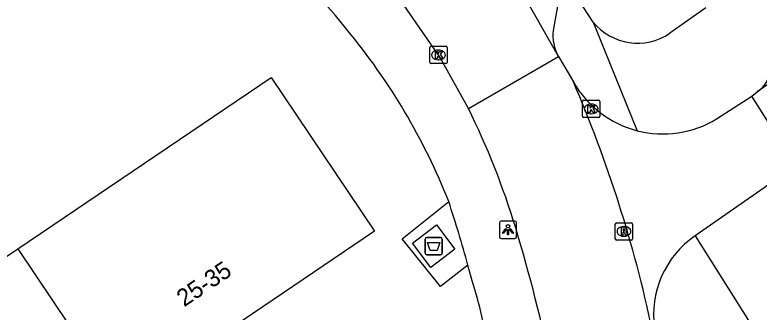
# Model space of a CAD drawing. Extents: x 157466 to 158888, y 383063 to 384677.
# Drawn here: x 157968.71 to 158011.77, y 383458.96 to 383476.12 of the extents above; entities that cross this region are included whole.
import ezdxf

# ---------------------------------------------------------------- set-up
doc = ezdxf.new("R2010")
doc.units = 0
for name, color, linetype in [('IMGEO_Afval_apart_plaats', 7, 'Continuous'), ('IMGEO_Kolk', 7, 'Continuous'), ('IMGEO_Lichtpunt', 7, 'Continuous'), ('IMGEO_Pand', 7, 'Continuous'), ('IMGEO_Pand_nummerreeks', 7, 'Continuous'), ('IMGEO_Rijbaan_lokaal_gesloten', 7, 'Continuous'), ('IMGEO_Rijbaan_lokaal_open', 7, 'Continuous'), ('IMGEO_Rioolput', 7, 'Continuous'), ('IMGEO_Voetpad_gesloten', 7, 'Continuous'), ('IMGEO_Voetpad_open', 7, 'Continuous')]:
    doc.layers.add(name, color=color, linetype=linetype)

msp = doc.modelspace()

# ---------------------------------------------------------------- linework, layer by layer
at = {"layer": 'IMGEO_Afval_apart_plaats'}
for p, q in [((157992.447, 383462.369), (157992.447, 383463.169)), ((157992.447, 383463.169), (157992.447, 383462.369)), ((157992.547, 383463.269), (157993.337, 383463.269)), ((157993.337, 383463.269), (157992.547, 383463.269)), ((157993.437, 383463.169), (157993.437, 383462.369)), ((157993.437, 383462.369), (157993.437, 383463.169)), ((157993.337, 383462.269), (157992.547, 383462.269)), ((157992.547, 383462.269), (157993.337, 383462.269))]:
    msp.add_line(p, q, dxfattribs=at)
msp.add_lwpolyline([(157992.59, 383462.983), (157993.294, 383462.983), (157993.145, 383462.513), (157992.739, 383462.513), (157992.59, 383462.983)], dxfattribs=at)
for centre, start, end in [((157992.547, 383463.169), 90, 180), ((157992.547, 383463.169), 90, 180), ((157993.337, 383463.169), 0, 90), ((157993.337, 383463.169), 360, 90), ((157992.547, 383462.369), 180, 270), ((157992.547, 383462.369), 180, 270), ((157993.337, 383462.369), 270, 0), ((157993.337, 383462.369), 270, 0)]:
    msp.add_arc(centre, 0.1, start, end, dxfattribs=at)
at = {"layer": 'IMGEO_Kolk'}
for p, q in [((157992.721, 383473.382), (157992.721, 383474.234)), ((157992.796, 383474.308), (157993.648, 383474.308)), ((157993.722, 383474.234), (157993.722, 383473.382)), ((157993.209, 383474.088), (157993.234, 383474.088)), ((157993.232, 383473.528), (157993.207, 383473.528)), ((157993.648, 383473.308), (157992.796, 383473.308)), ((158001.55, 383470.266), (158001.55, 383471.118)), ((158001.625, 383471.192), (158002.477, 383471.192)), ((158002.038, 383470.972), (158002.063, 383470.972)), ((158002.551, 383471.118), (158002.551, 383470.266)), ((158002.061, 383470.412), (158002.036, 383470.412)), ((158002.477, 383470.192), (158001.625, 383470.192))]:
    msp.add_line(p, q, dxfattribs=at)
for points in [[(157992.721, 383473.382), (157992.721, 383474.234)], [(157992.796, 383474.308), (157993.648, 383474.308)], [(157993.722, 383474.234), (157993.722, 383473.382)], [(157993.042, 383474.008), (157993.165, 383474.008), (157993.165, 383473.857), (157993.295, 383474.008), (157993.459, 383474.008), (157993.313, 383473.857), (157993.466, 383473.608), (157993.314, 383473.608), (157993.229, 383473.772), (157993.165, 383473.705), (157993.165, 383473.608), (157993.042, 383473.608), (157993.042, 383474.008)], [(157993.648, 383473.308), (157992.796, 383473.308)], [(158001.55, 383470.266), (158001.55, 383471.118)], [(158001.625, 383471.192), (158002.477, 383471.192)], [(158001.871, 383470.892), (158001.994, 383470.892), (158001.994, 383470.741), (158002.124, 383470.892), (158002.288, 383470.892), (158002.142, 383470.741), (158002.295, 383470.492), (158002.143, 383470.492), (158002.058, 383470.656), (158001.994, 383470.589), (158001.994, 383470.492), (158001.871, 383470.492), (158001.871, 383470.892)], [(158002.551, 383471.118), (158002.551, 383470.266)], [(158002.477, 383470.192), (158001.625, 383470.192)]]:
    msp.add_lwpolyline(points, dxfattribs=at)
for centre, start, end in [((157992.798, 383474.232), 91.552, 178.448), ((157992.798, 383474.232), 91.552, 178.448), ((157993.646, 383474.232), 1.552, 88.448), ((157993.646, 383474.232), 1.552, 88.448), ((157992.798, 383473.384), 181.552, 268.448), ((157992.798, 383473.384), 181.552, 268.448), ((157993.646, 383473.384), 271.552, 358.448), ((157993.646, 383473.384), 271.552, 358.448), ((158001.627, 383471.116), 91.552, 178.448), ((158001.627, 383471.116), 91.552, 178.448), ((158002.475, 383471.116), 1.552, 88.448), ((158002.475, 383471.116), 1.552, 88.448), ((158001.627, 383470.268), 181.552, 268.448), ((158001.627, 383470.268), 181.552, 268.448), ((158002.475, 383470.268), 271.552, 358.448), ((158002.475, 383470.268), 271.552, 358.448)]:
    msp.add_arc(centre, 0.0765, start, end, dxfattribs=at)
for centre, major_axis, ratio, start_param, end_param in [((157993.208, 383473.808), (-0.387, 0.002), 0.722429, 4.712389, 7.853982), ((157993.233, 383473.808), (-0.39, 0.002), 0.717154, 1.570796, 4.712389), ((158002.037, 383470.692), (-0.387, 0.002), 0.722429, 4.712389, 7.853982), ((158002.062, 383470.692), (-0.39, 0.002), 0.717154, 1.570796, 4.712389)]:
    msp.add_ellipse(centre, major_axis=major_axis, ratio=ratio, start_param=start_param, end_param=end_param, dxfattribs=at)
at = {"layer": 'IMGEO_Lichtpunt'}
for p, q in [((157996.743, 383464.118), (157996.743, 383463.311)), ((157996.743, 383464.118), (157996.743, 383463.311)), ((157997.645, 383464.213), (157996.837, 383464.213)), ((157997.645, 383464.213), (157996.837, 383464.213)), ((157997.739, 383463.311), (157997.739, 383464.118)), ((157997.739, 383463.311), (157997.739, 383464.118)), ((157996.837, 383463.217), (157997.645, 383463.217)), ((157996.837, 383463.217), (157997.645, 383463.217))]:
    msp.add_line(p, q, dxfattribs=at)
for points in [[(157997.117, 383463.782), (157997.156, 383463.754), (157996.968, 383463.492), (157996.93, 383463.519), (157997.117, 383463.782)], [(157997.219, 383463.734), (157997.266, 383463.734), (157997.266, 383463.412), (157997.219, 383463.412), (157997.219, 383463.734)], [(157997.329, 383463.754), (157997.367, 383463.781), (157997.554, 383463.519), (157997.515, 383463.491), (157997.329, 383463.754)]]:
    msp.add_lwpolyline(points, dxfattribs=at)
msp.add_circle((157997.242, 383463.916), 0.0994, dxfattribs=at)
for centre, start, end in [((157996.837, 383464.118), 90, 180), ((157996.837, 383464.118), 90, 180), ((157997.645, 383464.118), 0, 90), ((157997.645, 383464.118), 0, 90), ((157996.837, 383463.311), 180, 270), ((157996.837, 383463.311), 180, 270), ((157997.645, 383463.311), 270, 0), ((157997.645, 383463.311), 270, 360)]:
    msp.add_arc(centre, 0.0946, start, end, dxfattribs=at)
at = {"layer": 'IMGEO_Pand'}
for points in [[(157968.869, 383462.612), (157983.54, 383472.513), (157989.524, 383463.625), (157974.853, 383453.724)], [(157954.187, 383452.703), (157968.869, 383462.612)], [(157968.869, 383462.612), (157974.853, 383453.724)]]:
    msp.add_lwpolyline(points, dxfattribs=at)
at = {"layer": 'IMGEO_Rijbaan_lokaal_gesloten'}
for points in [[(157994.947, 383470.721), (157993.279, 383473.713), (157989.701, 383478.888), (157989.562, 383479.045)], [(158000.16, 383473.727), (157998.304, 383476.981)], [(157994.947, 383470.721), (158000.16, 383473.727)], [(158000.16, 383473.727), (158001.025, 383472.251)]]:
    msp.add_lwpolyline(points, dxfattribs=at)
for centre, radius, start, end in [((157953.862, 383450.404), 45.834, 17.0264, 26.3126), ((157897.758, 383433.829), 104.334, 12.05271, 16.7084)]:
    msp.add_arc(centre, radius, start, end, dxfattribs=at)
at = {"layer": 'IMGEO_Rijbaan_lokaal_open'}
for points in [[(158054.318, 383500.98), (158011.667, 383471.672)], [(158011.346, 383471.434), (158011.667, 383471.672)], [(158009.313, 383470.112), (158011.346, 383471.434)], [(158013.925, 383467.527), (158012.545, 383469.533), (158011.346, 383471.434)], [(158013.925, 383467.527), (158012.114, 383466.171), (158010.93, 383465.347), (158008.072, 383463.356)]]:
    msp.add_lwpolyline(points, dxfattribs=at)
for centre, radius, start, end in [((158006.213, 383475.223), 5.978, 209.805, 255.5226), ((157931.831, 383442.331), 75.386, 11.97242, 23.38412), ((158006.212, 383475.217), 5.972, 255.5108, 301.2763), ((158011.159, 383458.806), 5.498, 124.1575, 188.2644)]:
    msp.add_arc(centre, radius, start, end, dxfattribs=at)
at = {"layer": 'IMGEO_Rioolput'}
for p, q in [((158003.452, 383463.189), (158003.452, 383464.041)), ((158003.527, 383464.115), (158004.379, 383464.115)), ((158003.94, 383463.895), (158003.965, 383463.895)), ((158004.453, 383464.041), (158004.453, 383463.189)), ((158004.379, 383463.115), (158003.527, 383463.115)), ((158003.963, 383463.335), (158003.938, 383463.335))]:
    msp.add_line(p, q, dxfattribs=at)
for points in [[(158003.452, 383463.189), (158003.452, 383464.041)], [(158003.527, 383464.115), (158004.379, 383464.115)], [(158004.453, 383464.041), (158004.453, 383463.189)], [(158004.041, 383463.813), (158003.789, 383463.815), (158003.789, 383463.415)], [(158003.789, 383463.415), (158003.913, 383463.415), (158003.913, 383463.577), (158003.924, 383463.577)], [(158003.967, 383463.734), (158003.913, 383463.734), (158003.913, 383463.653)], [(158003.913, 383463.653), (158003.965, 383463.653)], [(158003.971, 383463.548), (158004.042, 383463.415), (158004.182, 383463.415), (158004.117, 383463.541)], [(158004.379, 383463.115), (158003.527, 383463.115)]]:
    msp.add_lwpolyline(points, dxfattribs=at)
for centre, radius, start, end in [((158003.529, 383464.039), 0.0765, 91.552, 178.448), ((158003.529, 383464.039), 0.0765, 91.552, 178.448), ((158004.377, 383464.039), 0.0765, 1.552, 88.448), ((158004.377, 383464.039), 0.0765, 1.552, 88.448), ((158003.923, 383463.524), 0.0533, 26.0293, 88.6989), ((158003.949, 383463.842), 0.19, 274.7715, 282.9687), ((158003.973, 383463.638), 0.0964, 77.0061, 93.1865), ((158003.987, 383463.695), 0.0378, 276.6634, 79.6772), ((158004.04, 383463.703), 0.109, 350.3612, 89.416), ((158004.038, 383463.703), 0.112, 277.5842, 350.9817), ((158004.022, 383463.488), 0.108, 29.5134, 73.7905), ((158003.529, 383463.191), 0.0765, 181.552, 268.448), ((158003.529, 383463.191), 0.0765, 181.552, 268.448), ((158004.377, 383463.191), 0.0765, 271.552, 358.448), ((158004.377, 383463.191), 0.0765, 271.552, 358.448)]:
    msp.add_arc(centre, radius, start, end, dxfattribs=at)
for centre, major_axis, ratio, start_param, end_param in [((158003.939, 383463.615), (-0.387, 0.002), 0.722429, 4.712389, 7.853982), ((158003.964, 383463.615), (-0.39, 0.002), 0.717154, 1.570796, 4.712389)]:
    msp.add_ellipse(centre, major_axis=major_axis, ratio=ratio, start_param=start_param, end_param=end_param, dxfattribs=at)
at = {"layer": 'IMGEO_Voetpad_gesloten'}
msp.add_lwpolyline([(157992.772, 383461.542), (157991.715, 383462.945), (157993.112, 383463.997), (157994.168, 383462.593), (157992.772, 383461.542)], dxfattribs=at)
at = {"layer": 'IMGEO_Voetpad_open'}
for points in [[(157987.912, 383475.276), (157987.268, 383476.084), (157968.545, 383497.269)], [(158002.173, 383475.705), (158001.595, 383476.585), (158000.729, 383478.273)], [(158000.203, 383477.185), (157999.854, 383475.228)], [(158008.693, 383476.539), (158006.601, 383475.068)], [(158002.173, 383475.705), (158004.718, 383469.434)], [(157994.923, 383461.673), (157993.343, 383460.443), (157991.123, 383463.196), (157993.811, 383465.338)], [(158008.072, 383463.356), (158013.037, 383455.497)], [(157995.174, 383460.762), (157994.923, 383461.673)]]:
    msp.add_lwpolyline(points, dxfattribs=at)
for centre, radius, start, end in [((158004.734, 383477.797), 3.307, 219.2458, 304.3817), ((157959.853, 383451.901), 36.52, 21.5886, 39.7965), ((158002.357, 383474.957), 2.518, 173.8112, 209.2341), ((158010.594, 383473.208), 1.874, 304.9402, 352.3233), ((157920.953, 383441.231), 76.743, 15.44849, 18.30823), ((157971.601, 383453.288), 24.729, 7.7794, 17.5926)]:
    msp.add_arc(centre, radius, start, end, dxfattribs=at)

# ---------------------------------------------------------------- texts
at = {"layer": 'IMGEO_Pand_nummerreeks'}
msp.add_text('25-35', height=1, rotation=34.0147, dxfattribs=at).set_placement((157978.503, 383459.227))

doc.saveas('drawing.dxf')
